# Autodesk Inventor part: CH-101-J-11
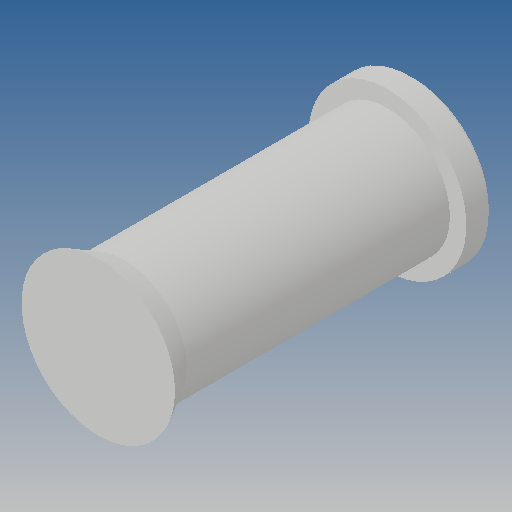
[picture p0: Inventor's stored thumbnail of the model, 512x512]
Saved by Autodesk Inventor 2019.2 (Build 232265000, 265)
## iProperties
Created: 2012-09
Part Number: CH-101-J-11
Material: Ogólny
Document SubType Name: Modeling
Designer: CADENGINEERING4
Density: 1 g/cm^3
Appearance: Domyślna
Author: CADENGINEERING4
Revision Number: ÈÎºÎ
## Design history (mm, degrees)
feature "µ¹½Ç1"
node "Bryła1"
